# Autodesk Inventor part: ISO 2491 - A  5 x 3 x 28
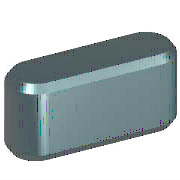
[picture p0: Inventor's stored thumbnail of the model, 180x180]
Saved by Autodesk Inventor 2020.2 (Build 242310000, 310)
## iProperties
Created: 2019-01
Part Number: ISO 2491 - A  5 x 3 x 28
Material: Stahl, weich
Description: Passfedern
Document SubType Name: Modeling
Standard: ISO 2491
Designer: lutzd
Standard Revision: First edition 1974-08-15
Standards Organization: ISO
Language: de-DE
Size Designation: A  5 x 3 x 28
Categories: <MemberInstance><Categories><Category DisplayName="Wellenteile" InternalName="7f7aeb1f-a693-4053-b835-cee3144e0d98" Mnemonic="SHFT"><Category DisplayName="Passf
Mass: 3.0942 g
Surface Area: 4.25059 cm^2
Volume: 0.394166 cm^3
Density: 7.85 g/cm^3
Appearance: Semi-Polished(8)
IsCustomPart: 0
Author: lutzd
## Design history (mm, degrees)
workplane "Work Plane1"
workplane "Work Plane2"
sketch "Skizze1"
  geometry: L1 (2.5, 2.5)-(25.5, 2.5); L2 (25.5, -2.5)-(2.5, -2.5); L3 (0, 9.4)-(0, -7.4) reference; L4 (-5, 0)-(30, 0) reference; L5 (28, 0)-(28, 7); A1 r 2.5 centre (2.5, 0) between (2.5, 2.5) and (2.5, -2.5); A2 r 2.5 centre (25.5, 0) between (25.5, -2.5) and (25.5, 2.5)
  constraints: 6 end point, 5 point on circle, 4 tangent, 3 point on line, 2 centre point, 1 horizontal, 1 parallel, 1 perpendicular
  dimensions: "d0" = 2.5 radius of A1 (= 0.5 x PB); "d13" = 2.5 radius of A2 (= 0.5 x PB); "d14" = 28 distance between parallel lines of L5 L3 (= NLG)
extrude "Körper1" new body sketch "Skizze1" taper "d3" = 0 deg; stored distance "d4" = 10
workplane "Work Plane3"
body "Solid1"
chamfer "Fase1" distance "d8" = 0.4 (= PHH); stored, may be unused: second distance "d9" = 0.4 (= PHH), angle "d15" = 45 deg
other parameters: "d1" = -1.8 (= -PNT), "d2" = 1.2 (= PH - PNT), "NLG" = 28 [user parameter; used in 1 equation term], "PB" = 5 [user parameter; used in 2 equation terms], "PNT" = 1.8 [user parameter; used in 2 equation terms], "PH" = 3 [user parameter; used in 1 equation term], "PHH" = 0.4 [user parameter; used in 2 equation terms], "d10" = 0, "d16" = 0, "d17" = 0, "d18" = 0, "RR" = 0.16 [user parameter], "WDMIN" = 12 [user parameter], "WDMAX" = 17 [user parameter], "PLB1" = 28 [user parameter], "PLB2" = 28 [user parameter], "PUEB" = 1.4 [user parameter]
